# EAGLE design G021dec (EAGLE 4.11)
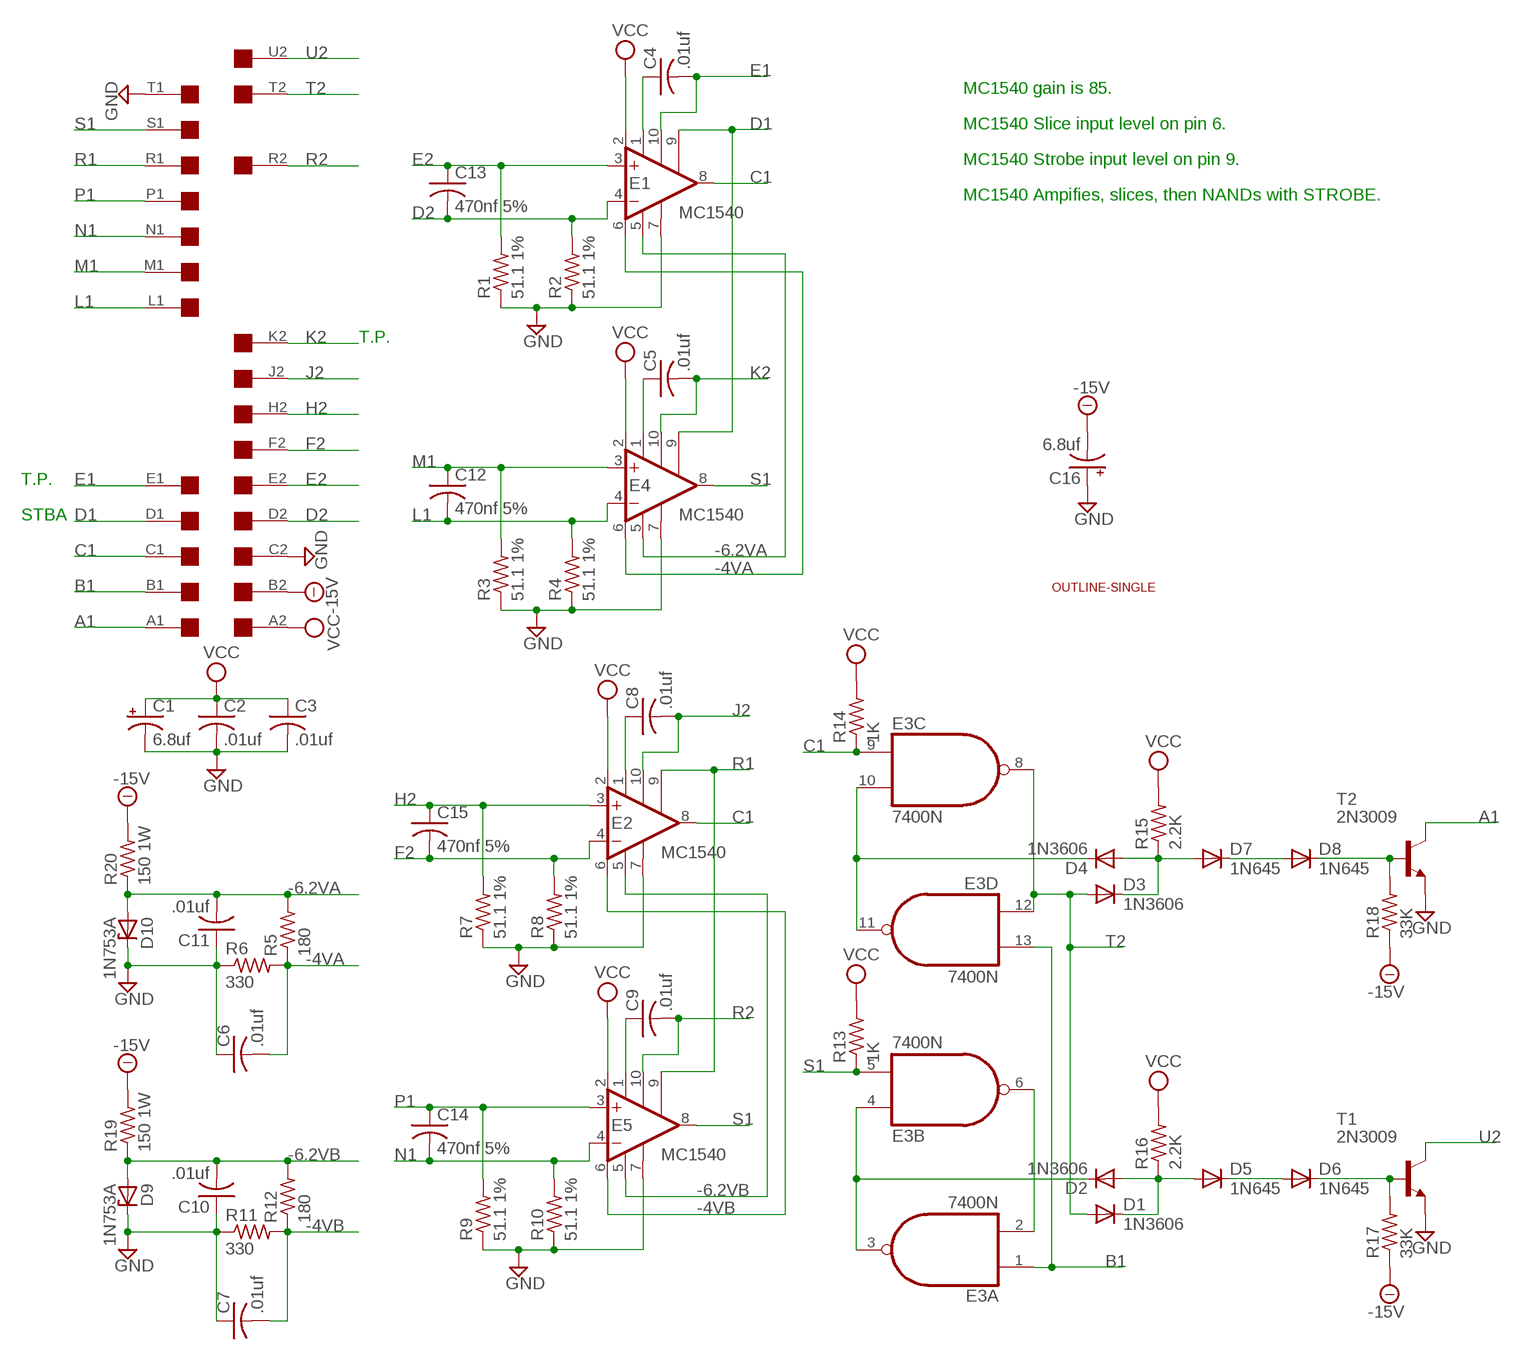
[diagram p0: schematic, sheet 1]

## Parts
C1  6.8uf  CPOL-USE15-5AXIAL  [E15-5]
C2  .01uf  C-US050-025X075  [C050-025X075]
C3  .01uf  C-US050-025X075  [C050-025X075]
C4  .01uf  C-US050-025X075  [C050-025X075]
C5  .01uf  C-US050-025X075  [C050-025X075]
C6  .01uf  C-US050-025X075  [C050-025X075]
C7  .01uf  C-US050-025X075  [C050-025X075]
C8  .01uf  C-US050-025X075  [C050-025X075]
C9  .01uf  C-US050-025X075  [C050-025X075]
C10  .01uf  C-US050-025X075  [C050-025X075]
C11  .01uf  C-US050-025X075  [C050-025X075]
C12  470nf 5%  C-US050-025X075  [C050-025X075]
C13  470nf 5%  C-US050-025X075  [C050-025X075]
C14  470nf 5%  C-US050-025X075  [C050-025X075]
C15  470nf 5%  C-US050-025X075  [C050-025X075]
C16  6.8uf  CPOL-USE15-5AXIAL  [E15-5]
D1  1N3606  1N4148  [DO35-10]
D2  1N3606  1N4148  [DO35-10]
D3  1N3606  1N4148  [DO35-10]
D4  1N3606  1N4148  [DO35-10]
D5  1N645  1N4148  [DO35-10]
D6  1N645  1N4148  [DO35-10]
D7  1N645  1N4148  [DO35-10]
D8  1N645  1N4148  [DO35-10]
D9  1N753A  ZENER-DIODEF126-10  [F126Z10]
D10  1N753A  ZENER-DIODEF126-10  [F126Z10]
E1  MC1540  [TO100]
E2  MC1540  [TO100]
E3  7400N  [DIL14]
E4  MC1540  [TO100]
E5  MC1540  [TO100]
R1  51.1 1%  R-US_0207/10  [0207/10]
R2  51.1 1%  R-US_0207/10  [0207/10]
R3  51.1 1%  R-US_0207/10  [0207/10]
R4  51.1 1%  R-US_0207/10  [0207/10]
R5  180  R-US_0207/10  [0207/10]
R6  330  R-US_0207/10  [0207/10]
R7  51.1 1%  R-US_0207/10  [0207/10]
R8  51.1 1%  R-US_0207/10  [0207/10]
R9  51.1 1%  R-US_0207/10  [0207/10]
R10  51.1 1%  R-US_0207/10  [0207/10]
R11  330  R-US_0207/10  [0207/10]
R12  180  R-US_0207/10  [0207/10]
R13  1K  R-US_0207/10  [0207/10]
R14  1K  R-US_0207/10  [0207/10]
R15  2.2K  R-US_0207/10  [0207/10]
R16  2.2K  R-US_0207/10  [0207/10]
R17  33K  R-US_0207/10  [0207/10]
R18  33K  R-US_0207/10  [0207/10]
R19  150 1W  R-US_0414/15  [0414/15]
R20  150 1W  R-US_0414/15  [0414/15]
T1  2N3009  2N3565  [TO92]
T2  2N3009  2N3565  [TO92]
U$1  SINGLE  [EDGE-CON2]
U$2  OUTLINE-SINGLE  [SINGLE]

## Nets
-4VA: C6.2 E1.6(SLICE) E4.6(SLICE) R5.1 R6.2
-4VB: C7.2 E2.6(SLICE) E5.6(SLICE) R11.2 R12.1
-6.2VA: C11.2 D10.A E1.5(V-) E4.5(V-) R5.2 R20.1
-6.2VB: C10.2 D9.A E2.5(V-) E5.5(V-) R12.2 R19.1
-15V: C16.- R17.1 R18.1 R19.2 R20.2 U$1.B2
A1: T2.1(C) U$1.A1
B1: E3.1(A:I0) E3.13(D:I1) U$1.B1
C1: E1.8(OUT) E2.8(OUT) E3.9(C:I0) R14.1 U$1.C1
D1: E1.9(ISTROBE) E4.9(ISTROBE) U$1.D1
D2: C13.2 E1.4(-IN) R2.2 U$1.D2
E1: C4.2 E1.10(CEXTB) U$1.E1
E2: C13.1 E1.3(+IN) R1.2 U$1.E2
F2: C15.2 E2.4(-IN) R8.2 U$1.F2
GND [supply]: C1.- C2.2 C3.2 C6.1 C7.1 C10.1 C11.1 C16.+ D9.C D10.C E1.7(GND) E2.7(GND) E4.7(GND) E5.7(GND) R1.1 R2.1 R3.1 R4.1 R6.1 R7.1 R8.1 R9.1 R10.1 R11.1 T1.3(E) T2.3(E) U$1.C2 U$1.T1
H2: C15.1 E2.3(+IN) R7.2 U$1.H2
J2: C8.2 E2.10(CEXTB) U$1.J2
K2: C5.2 E4.10(CEXTB) U$1.K2
L1: C12.2 E4.4(-IN) R4.2 U$1.L1
M1: C12.1 E4.3(+IN) R3.2 U$1.M1
N1: C14.2 E5.4(-IN) R10.2 U$1.N1
N$1: C4.1 E1.1(CEXTA)
N$2: C8.1 E2.1(CEXTA)
N$3: C5.1 E4.1(CEXTA)
N$4: C9.1 E5.1(CEXTA)
N$6: D1.C D2.A D5.A R16.1
N$7: D4.C E3.10(C:I1) E3.11(D:O)
N$8: D2.C E3.3(A:O) E3.4(B:I0)
N$9: E3.2(A:I1) E3.6(B:O)
N$10: D3.C D4.A D7.A R15.1
N$11: D7.C D8.A
N$12: D5.C D6.A
N$13: D8.C R18.2 T2.2(B)
N$14: D6.C R17.2 T1.2(B)
P1: C14.1 E5.3(+IN) R9.2 U$1.P1
R1: E2.9(ISTROBE) E5.9(ISTROBE) U$1.R1
R2: C9.2 E5.10(CEXTB) U$1.R2
S1: E3.5(B:I1) E4.8(OUT) E5.8(OUT) R13.1 U$1.S1
T2: D1.A D3.A E3.8(C:O) E3.12(D:I0) U$1.T2
U2: T1.1(C) U$1.U2
VCC [supply]: C1.+ C2.1 C3.1 E1.2(V+) E2.2(V+) E4.2(V+) E5.2(V+) R13.2 R14.2 R15.2 R16.2 U$1.A2
Unconnected: U$1.F1 U$1.H1 U$1.J1 U$1.K1 U$1.L2 U$1.M2 U$1.N2 U$1.P2 U$1.S2 U$1.U1 U$1.V1 U$1.V2

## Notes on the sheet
- MC1540 gain is 85.
- MC1540 Slice input level on pin 6.
- MC1540 Strobe input level on pin 9.
- MC1540 Ampifies, slices, then NANDs with STROBE.
- T.P.
- T.P.
- STBA

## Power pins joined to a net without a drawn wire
GND: E3.7(P:GND)
VCC: E3.14(P:VCC)

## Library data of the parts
C1 C16 = rcl:CPOL-US: POLARIZED CAPACITOR, American symbol
C2-C15 = rcl:C-US: CAPACITOR, American symbol
D1-D8 = diode:1N4148: DIODE
D9 D10 = diode:ZENER-DIODE: Z-Diode
E1 E2 E4 E5 = dec-con:MC1540: OP AMP
E3 = 74xx-us:74*00: Quad 2-input NAND gate
R1-R20 = rcl:R-US_: RESISTOR, American symbol
T1 T2 = transistor:2N3565: NPN TRANSISTOR
U$1 = dec-con:SINGLE: Double-Height DEC board
U$2 = dec-con:OUTLINE-*: Board outlines for DEC boards.

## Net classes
1 supply: width 0.762 mm, drill 0.635 mm

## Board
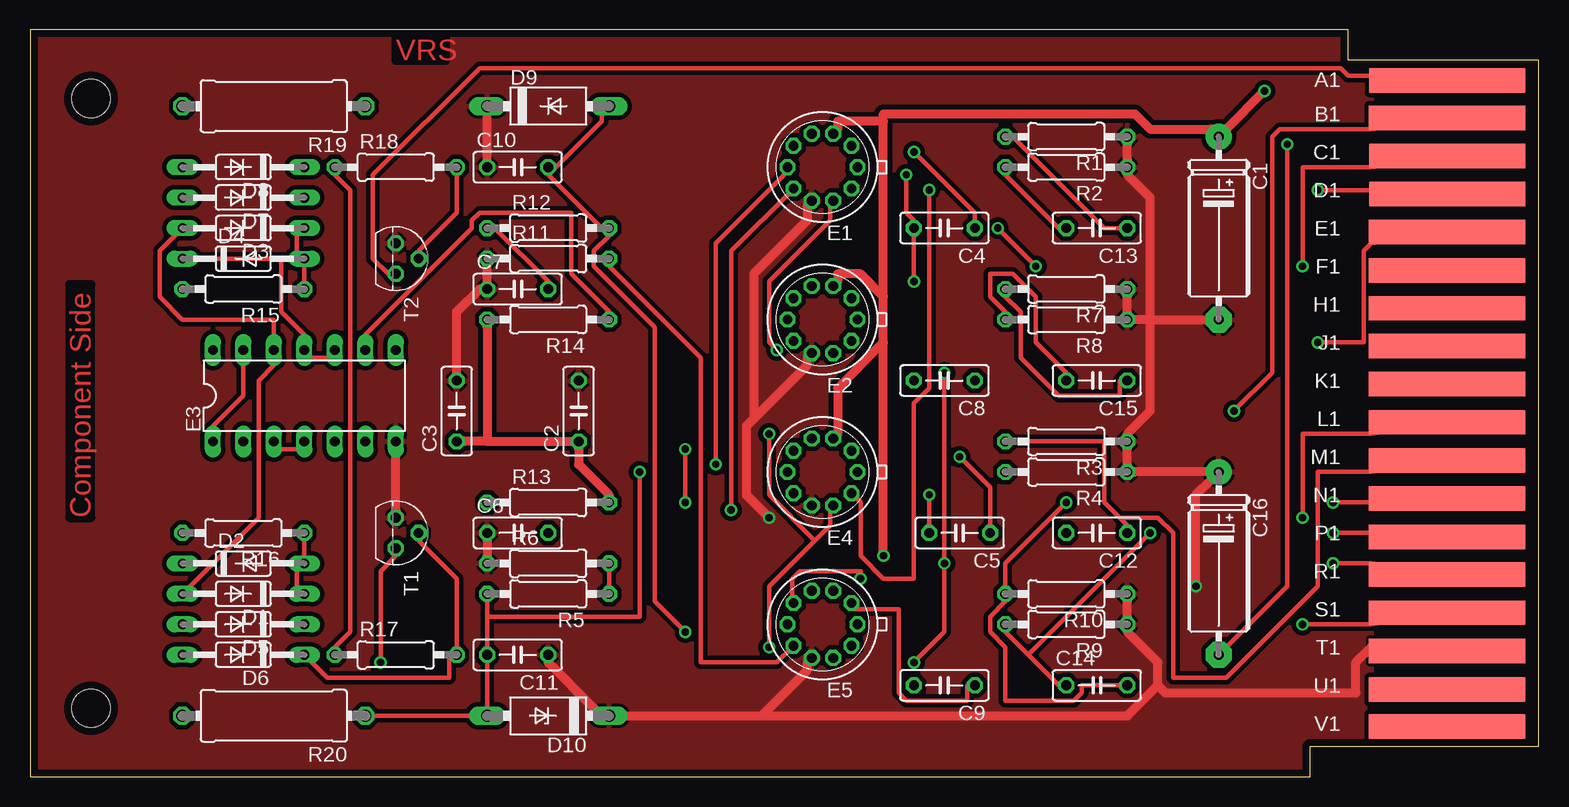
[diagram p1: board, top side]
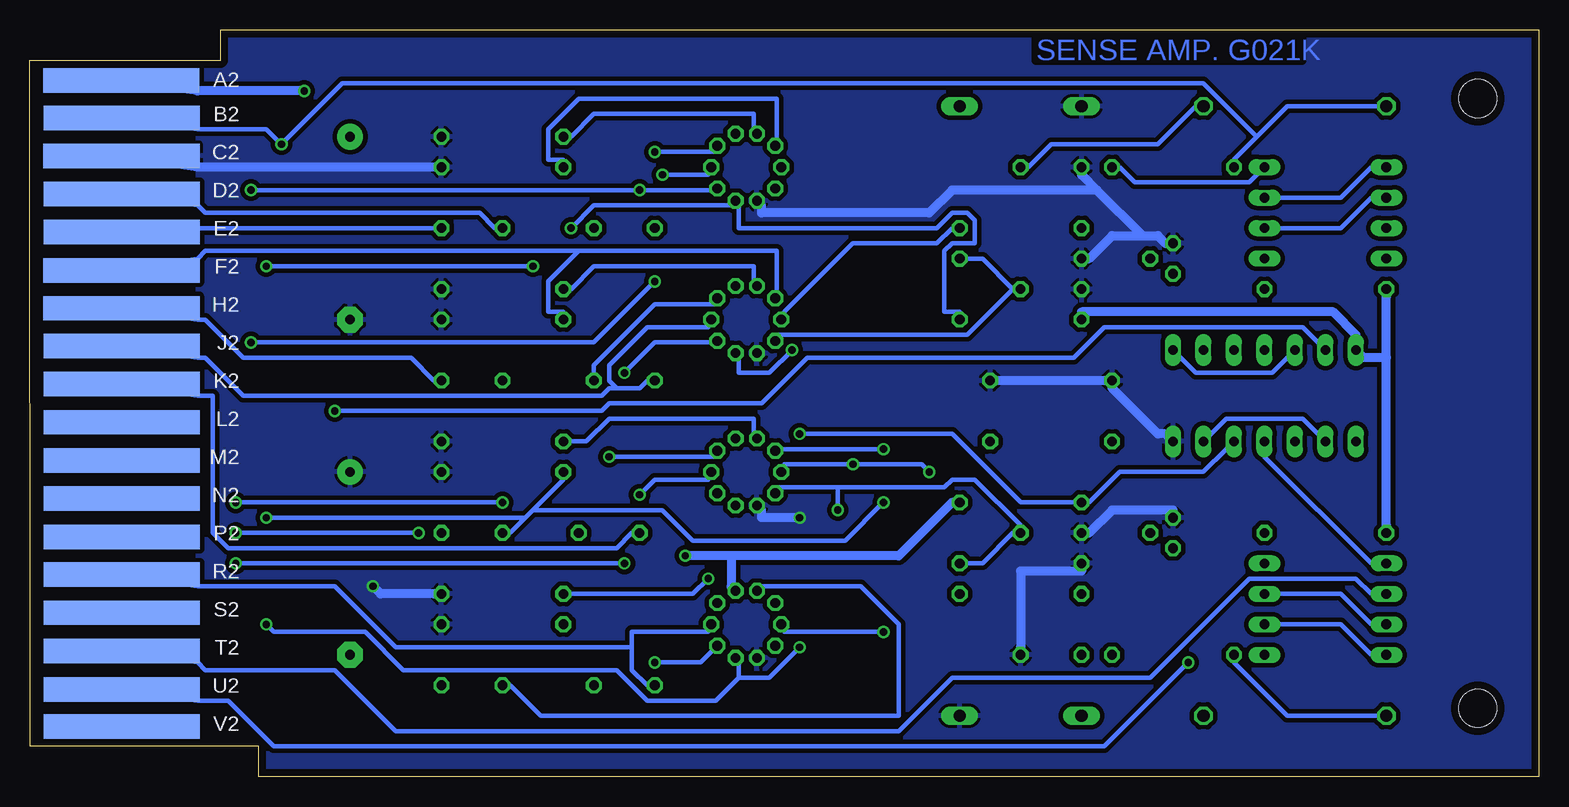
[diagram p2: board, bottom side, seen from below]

Size 125.73 x 62.23 mm. Coordinates in mm from the lower left corner, seen from the top.
Copper layers (1*16): Top 0.035mm / dielectric 1.5mm / Bottom 0.035mm
Design rules "15mils": minimum track width 15mil, minimum drill 24mil, track to track 15mil, track to pad 10mil, pad to pad 10mil, via to via 10mil, smd to smd 10mil, copper to edge 25mil, drill to drill 10mil, minimum pad ring 10mil, minimum via ring 8mil, stop-mask expansion 0mil, vias tented up to drill 0mil, thermal gap 10mil

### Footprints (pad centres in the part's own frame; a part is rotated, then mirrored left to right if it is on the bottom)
E15-5 = drill 0.813 pad 2.159 round: + -7.62,0 | drill 0.813 pad 2.159 octagon: - 7.62,0
C050-025X075 = drill 0.813 octagon: 1 -2.54,0; 2 2.54,0
DO35-10 = drill 0.813 long: A 5.08,0; C -5.08,0
F126Z10 = drill 1.016 long: A 5.08,0; C -5.08,0
TO100 = drill 0.813 octagon: 1 -2.413,-1.778; 2 -0.889,-2.794; 3 0.889,-2.794; 4 2.413,-1.778; 5 2.921,0; 6 2.413,1.778; 7 0.889,2.794; 8 -0.889,2.794; 9 -2.413,1.778; 10 -2.921,0
DIL14 = drill 0.813 long: 1 -7.62,-3.81; 2 -5.08,-3.81; 3 -2.54,-3.81; 4 0,-3.81; 5 2.54,-3.81; 6 5.08,-3.81; 7 7.62,-3.81; 8 7.62,3.81; 9 5.08,3.81; 10 2.54,3.81; 11 0,3.81; 12 -2.54,3.81; 13 -5.08,3.81; 14 -7.62,3.81
0207/10 = drill 0.813 octagon: 1 -5.08,0; 2 5.08,0
0414/15 = drill 1.016 octagon: 1 -7.62,0; 2 7.62,0
TO92 = drill 0.813 octagon: 1 1.27,0; 2 0,1.905; 3 -1.27,0
EDGE-CON2 = smd 13.017 x 2.032: A1 7.633,4.207; B1 7.639,7.327; C1 7.636,10.489; D1 7.633,13.665; E1 7.642,16.84; F1 7.642,20.041; H1 7.642,23.19; J1 7.642,26.34; K1 7.642,29.515; L1 7.642,32.69; M1 7.642,35.89; N1 7.642,39.04; P1 7.642,42.24; R1 7.642,45.39; S1 7.642,48.565; T1 7.642,51.74; U1 7.642,54.966; V1 7.642,58.026 | smd 13.017 x 2.032 bottom: A2 7.614,4.207; B2 7.642,7.328; C2 7.617,10.49; D2 7.642,13.665; E2 7.642,16.84; F2 7.617,20.041; H2 7.617,23.19; J2 7.642,26.34; K2 7.642,29.515; L2 7.642,32.69; M2 7.642,35.89; N2 7.642,39.04; P2 7.642,42.24; R2 7.642,45.39; S2 7.642,48.565; T2 7.642,51.74; U2 7.642,54.966; V2 7.642,58.026
SINGLE = hole 3.175: 120.65,56.515; 120.65,5.715

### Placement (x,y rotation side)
C1  99.06,45.72 270 top
C2  45.72,30.48 90 top
C3  35.56,30.48 90 top
C4  76.2,45.72 180 top
C5  77.47,20.32 180 top
C6  40.64,20.32 0 top
C7  40.64,40.64 0 top
C8  76.2,33.02 180 top
C9  76.2,7.62 180 top
C10  40.64,50.8 0 top
C11  40.64,10.16 180 top
C12  88.9,20.32 180 top
C13  88.9,45.72 180 top
C14  88.9,7.62 0 top
C15  88.9,33.02 180 top
C16  99.06,17.78 270 top
D1  17.78,15.24 180 top
D2  17.78,17.78 0 top
D3  17.78,45.72 180 top
D4  17.78,43.18 0 top
D5  17.78,12.7 180 top
D6  17.78,10.16 180 top
D7  17.78,48.26 180 top
D8  17.78,50.8 180 top
D9  43.18,55.88 0 top
D10  43.18,5.08 180 top
E1  66.04,50.8 180 top
E2  66.04,38.1 180 top
E3  22.86,31.75 0 top
E4  66.04,25.4 180 top
E5  66.04,12.7 180 top
R1  86.36,53.34 180 top
R2  86.36,50.8 180 top
R3  86.36,27.94 180 top
R4  86.36,25.4 180 top
R5  43.18,15.24 180 top
R6  43.18,17.78 0 top
R7  86.36,40.64 180 top
R8  86.36,38.1 180 top
R9  86.36,12.7 180 top
R10  86.36,15.24 180 top
R11  43.18,43.18 0 top
R12  43.18,45.72 0 top
R13  43.18,22.86 0 top
R14  43.18,38.1 180 top
R15  17.78,40.64 180 top
R16  17.78,20.32 180 top
R17  30.48,10.16 0 top
R18  30.48,50.8 0 top
R19  20.32,55.88 180 top
R20  20.32,5.08 180 top
T1  30.48,20.32 270 top
T2  30.48,43.18 270 top
U$1  125.73,62.23 180 top
U$2  125.73,62.23 180 top

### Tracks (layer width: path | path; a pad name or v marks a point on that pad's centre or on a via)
-4VA  (via drill 0.61)
  Top 0.381: R5.1 48.26,15.88 48.26,17.14 R6.2 | v58.42,22.23 58.42,43.81 63.5,48.9 E1.6
  Bottom 0.381: R6.2 47.62,17.78 46.35,17.78 43.81,20.32 C6.2 43.18,20.95 46.99,24.77 48.9,24.77 49.53,24.13 58.42,24.13 | 58.42,24.13 63.5,24.13 E4.6 | 58.42,24.13 v58.42,22.23
-4VB
  Top 0.381: E5.6 63.5,10.79 62.23,9.53 55.88,9.53 55.88,34.92 48.26,42.55 R11.2 | R12.1 38.73,45.72 43.18,41.27 C7.2
  Bottom 0.381: 43.81,40.64 46.35,43.18 47.62,43.18 R11.2 | 43.81,40.64 C7.2 43.81,40.64 | 43.81,40.64 47.62,36.83 63.5,36.83 E2.6
-6.2VA  (via drill 0.61)
  Top 0.381: 38.1,13.34 38.1,10.79 C11.2 38.1,9.53 38.1,5.71 D10.A 36.83,5.08 28.57,5.08 R20.1 | 38.1,13.34 38.1,14.61 R5.2 | v57.15,26.04 57.15,44.45 62.87,50.16 E1.5 | 38.1,13.34 50.8,13.34 v50.8,25.4
  Bottom 0.381: E4.5 62.87,26.04 v57.15,26.04 51.44,26.04 v50.8,25.4
-6.2VB  (via drill 0.61)
  Top 0.381: D9.A 47.62,55.24 47.62,54.61 43.81,50.8 C10.2 43.18,50.16 47.62,45.72 R12.2 48.26,45.09 46.99,43.81 46.99,42.55 52.07,37.47 52.07,14.61 v54.61,12.06
  Bottom 0.381: R19.1 28.57,55.88 31.75,52.7 40.64,52.7 42.55,50.8 C10.2 | v54.61,12.06 62.87,12.06 E5.5 | E2.5 62.87,38.73 57.15,44.45 50.16,44.45 48.9,45.72 R12.2
-15V  (via drill 0.61)
  Top 0.381: R17.1 25.4,10.79 26.67,12.06 26.67,48.9 25.4,50.16 R18.1 | v104.78,52.7 104.78,15.88 99.69,10.79 C16.-
  Bottom 0.381: R17.1 25.4,9.53 20.95,5.08 13.34,5.08 R20.2 | 23.5,53.34 20.95,55.88 13.34,55.88 R19.2 | 23.5,53.34 25.4,51.44 R18.1 | U$1.B2 111.76,53.98 106.05,53.98 v104.78,52.7 99.69,57.78 27.94,57.78 23.5,53.34
A1
  Top 0.381: T2.1 29.84,41.91 28.57,43.18 28.57,50.16 37.47,59.05 109.22,59.05 109.86,58.42 111.76,58.42 U$1.A1
B1  (via drill 0.61)
  Top 0.381: E3.1 15.24,29.21 17.78,31.75 17.78,34.29 E3.13 | v100.33,30.48 103.5,33.66 103.5,53.34 104.14,53.98 111.76,53.98 U$1.B1
  Bottom 0.381: v100.33,30.48 78.11,30.48 77.47,31.11 64.77,31.11 60.96,34.92 38.73,34.92 36.2,37.47 19.68,37.47 18.41,36.2 E3.13
C1  (via drill 0.61)
  Top 0.381: v62.23,35.56 61.59,36.2 61.59,41.27 66.67,46.35 66.67,47.62 E1.8 | E3.9 27.94,36.83 36.83,45.72 36.83,46.35 37.47,46.99 45.09,46.99 45.09,41.91 48.26,38.73 R14.1 | v106.05,42.55 106.05,50.8 111.76,50.8 U$1.C1 | v80.64,45.72 v83.82,42.55
  Bottom 0.381: v62.23,35.56 64.14,33.66 66.67,33.66 66.67,34.92 E2.8 | R14.1 48.26,38.73 49.53,38.73 49.53,43.81 48.9,44.45 46.99,44.45 46.99,46.35 47.62,46.99 48.9,46.99 50.16,45.72 66.67,45.72 66.67,47.62 E1.8 67.31,47.62 78.74,47.62 v80.64,45.72 | v83.82,42.55 v106.05,42.55
D1  (via drill 0.61)
  Top 0.381: v74.93,48.9 74.93,32.38 73.66,31.11 73.66,16.51 71.12,16.51 69.22,18.41 69.22,22.86 68.58,23.5 E4.9 | v107.31,48.9 111.76,48.9 U$1.D1
  Bottom 0.381: E1.9 68.58,48.9 v74.93,48.9 v107.31,48.9
D2
  Top 0.381: C13.2 85.72,45.72 81.28,50.16 R2.2
  Bottom 0.381: E1.4 63.5,52.7 63.5,56.52 80.01,56.52 82.55,53.98 82.55,51.44 81.28,51.44 R2.2 | U$1.D2 111.76,47.62 111.12,46.99 88.27,46.99 87,45.72 C13.2
E1  (via drill 0.61)
  Top 0.381: v73.03,50.16 73.03,46.99 73.66,46.35 C4.2 73.66,45.09 v73.66,41.27 | v107.31,36.2 111.12,36.2 111.12,43.81 111.76,44.45 U$1.E1
  Bottom 0.381: v73.03,50.16 69.22,50.16 E1.10 | v73.66,41.27 78.74,36.2 v107.31,36.2
E2
  Top 0.381: R1.2 81.92,53.34 89.53,45.72 90.81,45.72 C13.1
  Bottom 0.381: E1.3 65.41,53.98 65.41,55.24 78.74,55.24 80.64,53.34 R1.2 | U$1.E2 111.76,45.72 92.08,45.72 C13.1
F2
  Top 0.381: C15.2 86.36,33.66 83.82,36.2 83.82,40.01 81.92,41.91 80.01,41.91 80.01,40.01 81.28,38.73 R8.2
  Bottom 0.381: 80.01,43.81 63.5,43.81 63.5,40.01 E2.4 | 80.01,43.81 82.55,41.27 82.55,38.73 81.28,38.73 R8.2 | 80.01,43.81 111.12,43.81 111.76,43.18 U$1.F2
GND  (via drill 0.61)
  Top 0.762: R1.1 91.44,52.7 91.44,51.44 R2.1 91.44,50.16 93.34,48.26 93.34,38.1 | R7.1 91.44,40.01 91.44,38.73 R8.1 92.08,38.1 93.34,38.1 | 93.34,38.1 98.42,38.1 C1.- | 93.34,38.1 93.34,30.48 91.44,28.57 R3.1 91.44,27.3 91.44,26.04 R4.1 92.08,25.4 98.42,25.4 C16.+ 98.42,24.77 97.16,23.5 v97.16,15.88 | R10.1 91.44,14.61 91.44,13.34 R9.1 91.44,12.06 93.98,9.53 93.98,7.62 | 93.98,7.62 94.61,6.99 110.49,6.99 110.49,9.53 111.76,10.79 U$1.T1 | v61.59,21.59 59.69,23.5 59.69,29.21 60.33,29.84 | 60.33,29.84 64.77,34.29 64.77,34.92 E2.7 | 60.33,29.84 60.33,41.91 64.77,46.35 64.77,47.62 E1.7 | C11.1 43.18,9.53 46.99,5.71 46.99,5.08 D10.C 49.53,5.08 60.96,5.08 | 60.96,5.08 64.77,8.89 64.77,9.53 E5.7 | C10.1 38.1,51.44 38.1,55.24 D9.C | R11.1 38.1,42.55 38.1,41.27 C7.1 37.47,40.64 35.56,38.73 35.56,33.66 C3.2 | R6.1 38.1,18.41 38.1,19.68 C6.1 | T1.3 30.48,22.23 30.48,26.67 E3.7 | 93.98,7.62 91.44,5.08 60.96,5.08
  Bottom 0.762: U$1.C2 111.76,50.8 92.08,50.8 R2.1 | v61.59,21.59 64.77,21.59 64.77,22.23 E4.7 | 33.02,45.09 35.56,45.09 37.47,43.18 R11.1 | 33.02,45.09 31.75,45.09 31.11,44.45 T2.3 | 33.02,45.09 36.83,48.9 | 36.83,48.9 38.1,50.16 C10.1 | E3.7 31.11,28.57 31.75,28.57 35.56,32.38 C3.2 36.2,33.02 45.09,33.02 C2.2 | C6.1 37.47,20.32 35.56,22.23 30.48,22.23 T1.3 | C11.1 43.18,10.79 43.18,17.14 38.1,17.14 R6.1 | 36.83,48.9 48.9,48.9 50.8,46.99 64.77,46.99 64.77,47.62 E1.7 | v97.16,15.88 96.52,15.24 92.08,15.24 R10.1
  pour Top: 0,62.23 111.76,62.23 111.76,0 0,0
  pour Bottom: 0,62.23 111.76,62.23 111.76,0 0,0
H2
  Top 0.381: R7.2 81.28,40.01 82.55,38.73 82.55,34.92 85.72,31.75 90.81,31.75 90.81,33.02 C15.1
  Bottom 0.381: C15.1 92.08,33.02 93.98,34.92 107.95,34.92 111.12,38.1 111.76,38.1 U$1.H2 | E2.3 65.41,41.27 65.41,42.55 78.74,42.55 80.64,40.64 R7.2
J2
  Bottom 0.381: 76.83,32.38 74.93,32.38 74.3,33.02 C8.2 | 76.83,32.38 77.47,33.02 77.47,34.29 74.3,37.47 69.22,37.47 E2.10 | 76.83,32.38 77.47,32.38 78.11,31.75 107.95,31.75 111.12,34.92 111.76,34.92 U$1.J2
K2  (via drill 0.61)
  Top 0.381: v74.93,23.5 74.93,20.95 C5.2
  Bottom 0.381: v74.93,23.5 73.66,24.77 69.22,24.77 E4.10 | C5.2 75.56,20.32 76.83,19.05 109.22,19.05 110.49,20.32 110.49,31.75 111.76,31.75 U$1.K2
L1  (via drill 0.61)
  Top 0.381: v54.61,22.86 v54.61,27.3 | v106.05,21.59 106.05,28.57 111.76,28.57 U$1.L1
  Bottom 0.381: 83.82,22.23 81.28,24.77 R4.2 | 83.82,22.23 84.45,21.59 | 84.45,21.59 85.72,20.32 C12.2 | v54.61,27.3 63.5,27.3 E4.4 | v54.61,22.86 57.78,19.68 70.48,19.68 73.03,22.23 83.82,22.23 | 84.45,21.59 v106.05,21.59
M1
  Top 0.381: 90.81,21.59 91.44,20.95 C12.1 | 90.81,21.59 89.53,22.86 89.53,27.94 81.92,27.94 R3.2 | 90.81,21.59 93.98,21.59 95.25,20.32 95.25,8.26 99.69,8.26 107.31,15.88 107.31,25.4 111.76,25.4 U$1.M1
  Bottom 0.381: E4.3 65.41,28.57 65.41,29.84 77.47,29.84 79.38,27.94 80.64,27.94 R3.2
N1  (via drill 0.61)
  Top 0.381: v69.22,16.51 69.22,17.14 64.14,17.14 63.5,16.51 63.5,14.61 E5.4 | C14.2 90.81,7.62 87.63,7.62 87.63,6.99 87,6.35 81.28,6.35 81.28,10.79 80.01,12.06 80.01,13.34 81.28,14.61 R10.2 81.28,15.88 81.28,17.78 v86.36,22.86 | v108.58,22.86 111.76,22.86 U$1.N1
  Bottom 0.381: v69.22,16.51 70.48,15.24 80.64,15.24 R10.2 | v86.36,22.86 v108.58,22.86
N$1  (via drill 0.61)
  Top 0.381: v73.66,52.07 78.74,46.99 78.74,46.35 C4.1
  Bottom 0.381: v73.66,52.07 68.58,52.07 E1.1
N$2
  Bottom 0.381: E2.1 68.58,39.37 73.66,39.37 78.74,34.29 78.74,33.66 C8.1
N$3  (via drill 0.61)
  Top 0.381: v77.47,26.67 80.01,24.13 80.01,20.95 C5.1
  Bottom 0.381: v77.47,26.67 68.58,26.67 E4.1
N$4
  Top 0.381: E5.1 68.58,13.97 72.39,13.97 72.39,6.99 73.03,6.35 78.11,6.35 78.11,7.62 C9.1
N$6
  Top 0.381: D1.C 22.23,15.88 22.23,17.14 D2.A 22.86,18.41 22.86,19.68 R16.1
  Bottom 0.381: D5.A 13.97,12.7 16.51,15.24 21.59,15.24 D1.C
N$7
  Top 0.381: E3.10 24.77,34.92 23.5,34.92 E3.11 22.86,36.83 20.95,38.73 20.95,43.18 13.97,43.18 D4.C
N$8
  Top 0.381: E3.3 20.95,27.3 22.23,27.3 E3.4
  Bottom 0.381: D2.C 13.97,17.78 22.86,26.67 E3.4
N$9
  Bottom 0.381: E3.2 18.41,28.57 19.68,29.84 26.04,29.84 27.3,28.57 E3.6
N$10
  Top 0.381: R15.1 22.86,41.27 22.86,42.55 D4.A 22.23,43.81 22.23,45.09 D3.C
  Bottom 0.381: D7.A 13.97,48.26 16.51,45.72 21.59,45.72 D3.C
N$11
  Bottom 0.381: D8.A 13.97,50.8 16.51,48.26 21.59,48.26 D7.C
N$12
  Bottom 0.381: D6.A 13.97,10.16 16.51,12.7 21.59,12.7 D5.C
N$13
  Top 0.381: T2.2 32.38,43.81 35.56,46.99 35.56,50.16 R18.2
  Bottom 0.381: D8.C 23.5,50.16 24.13,49.53 33.66,49.53 34.92,50.8 R18.2
N$14
  Top 0.381: D6.C 23.5,9.53 24.77,8.26 34.92,8.26 34.92,10.16 R17.2 35.56,10.79 35.56,16.51 32.38,19.68 T1.2
P1  (via drill 0.61)
  Top 0.381: 83.19,10.16 85.72,7.62 C14.1 | 83.19,10.16 81.28,12.06 R9.2 | v108.58,20.32 111.76,20.32 U$1.P1 | 83.19,10.16 v93.34,20.32
  Bottom 0.381: E5.3 64.77,15.88 56.52,15.88 53.34,12.7 53.34,5.08 83.19,5.08 85.72,7.62 C14.1 | v93.34,20.32 v108.58,20.32
R1  (via drill 0.61)
  Top 0.381: v73.66,9.53 76.2,12.06 v76.2,17.78 v76.2,33.66 | v108.58,17.78 111.76,17.78 U$1.R1
  Bottom 0.381: v73.66,9.53 69.85,9.53 68.58,10.79 E5.9 | v76.2,33.66 73.66,36.2 68.58,36.2 E2.9 | v76.2,17.78 v108.58,17.78
R2
  Bottom 0.381: 75.56,10.79 75.56,12.06 69.22,12.06 E5.10 | 75.56,10.79 75.56,8.89 74.3,7.62 C9.2 | 75.56,10.79 95.25,10.79 100.33,15.88 111.76,15.88 U$1.R2
S1  (via drill 0.61)
  Top 0.381: v61.59,10.79 61.59,15.88 65.41,19.68 | 65.41,19.68 66.67,20.95 66.67,22.23 E4.8 | 65.41,19.68 61.59,23.5 v61.59,28.57 | v106.05,12.7 111.76,12.7 U$1.S1
  Bottom 0.381: 66.67,8.26 66.67,9.53 E5.8 | 66.67,8.26 64.14,8.26 v61.59,10.79 | E3.5 26.04,27.3 27.94,25.4 34.92,25.4 37.47,22.86 R13.1 38.73,22.86 43.18,22.86 48.9,28.57 v61.59,28.57 | v106.05,12.7 105.41,12.06 97.79,12.06 94.61,8.89 76.83,8.89 74.3,6.35 68.58,6.35 66.67,8.26
T2
  Top 0.381: D1.A 13.34,15.88 19.05,21.59 19.05,33.02 20.32,34.29 E3.12 20.32,36.83 20.32,38.1 12.7,38.1 10.79,40.01 10.79,43.81 12.06,45.09 D3.A
  Bottom 0.381: E3.8 29.84,34.92 28.57,33.66 22.23,33.66 20.95,34.92 E3.12 | U$1.T2 111.76,9.53 111.12,8.89 100.33,8.89 95.25,3.81 53.34,3.81 48.9,8.26 32.38,8.26 24.13,16.51 15.24,16.51 13.97,15.24 D1.A
U2  (via drill 0.61)
  Top 0.381: v29.21,9.53 29.21,17.14 30.48,18.41 T1.1
  Bottom 0.381: v29.21,9.53 36.2,2.54 105.41,2.54 109.22,6.35 111.76,6.35 U$1.U2
VCC  (via drill 0.61)
  Top 0.762: 38.1,27.94 45.09,27.94 C2.1 45.72,27.3 45.72,26.04 48.26,23.5 R13.2 | 38.1,27.94 36.2,27.94 C3.1 | 38.1,27.94 38.1,37.47 R14.2 | 71.12,36.2 67.31,32.38 67.31,28.57 E4.2 | 71.12,36.2 71.12,40.01 | 71.12,40.01 69.22,41.91 67.31,41.91 67.31,41.27 E2.2 | 71.12,54.61 67.31,54.61 67.31,53.98 E1.2 | 71.12,40.01 71.12,54.61 | 71.12,54.61 71.12,55.24 92.08,55.24 93.34,53.98 98.42,53.98 C1.+ 99.69,53.98 v102.87,57.15 | v71.12,18.41 71.12,36.2
  Bottom 0.762: 12.7,34.92 12.7,20.95 R16.2 | 12.7,34.92 14.61,34.92 E3.14 15.24,36.83 17.14,38.73 38.1,38.73 R14.2 | 12.7,34.92 12.7,40.01 R15.2 | 67.31,18.41 67.31,15.88 E5.2 | 67.31,18.41 53.34,18.41 48.9,22.86 R13.2 | v102.87,57.15 111.76,57.15 U$1.A2 | 67.31,18.41 v71.12,18.41

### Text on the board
Top: VRS | Component Side
Bottom: SENSE AMP. G021K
